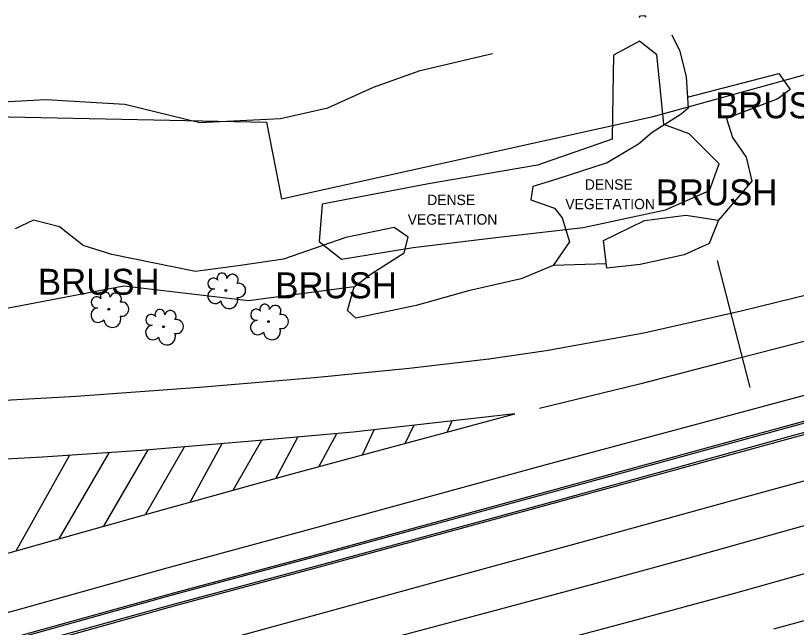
# Model space of a CAD drawing. Extents: x 2129547 to 2134906, y 657330 to 659734.
# Drawn here: x 2133105.5 to 2133315.8, y 658769 to 658933.8 of the extents above; entities that cross this region are included whole.
import ezdxf

# ---------------------------------------------------------------- set-up
doc = ezdxf.new("R2010")
doc.units = 0
for name, color, linetype in [('Default', 7, 'Continuous'), ('DR_X_Culvert', 7, 'Continuous'), ('PM_X_Edge_Line', 7, 'Continuous'), ('PM_X_Lane_Line', 7, 'Continuous'), ('PM_X_Transverse_Line', 7, 'Continuous'), ('PV_X_Curb', 7, 'Continuous'), ('PV_X_EOP2', 7, 'Continuous'), ('PV_X_Shoulder', 7, 'Continuous'), ('RD_X_Fence', 7, 'Continuous'), ('RD_X_Misc_Items', 7, 'Continuous'), ('SN_X_Cantilever_Overhead', 7, 'Continuous'), ('VG_X_Cells', 7, 'Continuous'), ('VG_X_Shrub_Line_Lt', 7, 'Continuous'), ('VG_X_Text', 7, 'Continuous'), ('VG_X_Tree_Line_Lt', 7, 'Continuous')]:
    doc.layers.add(name, color=color, linetype=linetype)

# ---------------------------------------------------------------- blocks, each defined once
blk = doc.blocks.new('CULVERT')
at = {"layer": 'Default'}
blk.add_lwpolyline([(-0.0508, 0.1143), (0, 0.0635), (0, -0.0635), (-0.0508, -0.1143)], dxfattribs=at)
blk = doc.blocks.new('TREE')
at = {"layer": 'VG_X_Cells'}
blk.add_circle((0, 0), 0.00305, dxfattribs=at)
for centre, radius, start, end in [((-0.0125, 0.0428), 0.0167, 354.0047, 205.9741), ((0.0232, 0.0359), 0.0197, 323.83, 165.0376), ((-0.042, 0.0237), 0.0187, 39.0625, 279.5412), ((-0.0362, -0.0197), 0.0251, 96.1722, 320.5737), ((0.0439, 0.0005), 0.0243, 259.1453, 101.4596), ((0.012, -0.0331), 0.029, 184.9476, 19.4572)]:
    blk.add_arc(centre, radius, start, end, dxfattribs=at)

msp = doc.modelspace()

# ---------------------------------------------------------------- linework, layer by layer
at = {"layer": 'PM_X_Edge_Line'}
for points in [[(2133329.04, 658861.1), (2133300.92, 658854.17), (2133274.71, 658848.24), (2133248.43, 658843.47), (2133232.93, 658841.23), (2133211.46, 658838.73), (2133186.01, 658836.22), (2133155.02, 658833.66), (2133121.79, 658831.17), (2133086.55, 658829.19), (2133054.09, 658828.41), (2133019.86, 658828.5), (2132985.53, 658829.46), (2132952.85, 658830.98), (2132915.52, 658833.61), (2132887.18, 658836.26), (2132858.31, 658839.93), (2132829.74, 658844.45), (2132808.54, 658848.31), (2132773.75, 658855.57)], [(2133352.86, 658840.89), (2133312.19, 658829.94), (2133247.7, 658812.58), (2133183.7, 658795.08), (2133146.25, 658784.96), (2133107.51, 658774.1), (2133073.85, 658764.93), (2133041.79, 658756.19), (2133011.05, 658747.8), (2132979.94, 658739.33), (2132948.72, 658730.94), (2132917.57, 658722.29), (2132887.16, 658713.87), (2132857, 658705.5), (2132818.68, 658695.21), (2132780.46, 658684.71), (2132740.98, 658673.64), (2132705.56, 658663.7), (2132666.4, 658652.81), (2132631.49, 658643.36), (2132595.52, 658633.47), (2132567.08, 658625.72), (2132529.28, 658615.18)], [(2133006.99, 658762.7), (2133037.72, 658771.1), (2133069.79, 658779.83), (2133103.39, 658788.99), (2133142.1, 658799.84), (2133179.64, 658810.26), (2133239.99, 658826.51), (2133196.39, 658821.58), (2133169.12, 658819.19), (2133139.39, 658816.63), (2133112.72, 658814.83), (2133086.2, 658813.46), (2133064.26, 658812.76), (2133033.29, 658812.66), (2133005.07, 658813.03), (2132970.88, 658814.09), (2132935.7, 658815.58), (2132903.64, 658817.26), (2132872, 658819.38), (2132835.28, 658822.67), (2132809.95, 658825.67), (2132783.95, 658829.71)], [(2132528.76, 658591.3), (2132572.65, 658603.2), (2132602.55, 658611.29), (2132644.66, 658622.9), (2132678.49, 658632.23), (2132709.33, 658640.79), (2132742.09, 658649.84), (2132779.08, 658660.22), (2132814.09, 658669.97), (2132851.16, 658680.16), (2132885.72, 658689.68), (2132917.4, 658698.33), (2132953.49, 658708.38), (2132988.45, 658717.87), (2133023.88, 658727.48), (2133061.03, 658737.93), (2133108.53, 658751.04), (2133150.67, 658762.63), (2133188.97, 658773.11), (2133222.93, 658782.47), (2133258.8, 658792.21), (2133300.07, 658803.6), (2133337.89, 658813.96)], [(2133309.7, 658768.6), (2133347.5, 658778.96)]]:
    msp.add_lwpolyline(points, dxfattribs=at)
at = {"layer": 'PM_X_Lane_Line'}
for points in [[(2133325.82, 658848.04), (2133297.69, 658840.83), (2133273.51, 658834.53), (2133246.62, 658827.98)], [(2133202.56, 658765), (2133233.48, 658773.28), (2133261.59, 658780.83), (2133286.58, 658787.68), (2133313.7, 658795.31), (2133339, 658802.3)], [(2133325.2, 658785.49), (2133298.77, 658778.04), (2133270.18, 658770.37), (2133241.97, 658762.79)]]:
    msp.add_lwpolyline(points, dxfattribs=at)
at = {"layer": 'PM_X_Transverse_Line'}
for p, q in [((2133221.73, 658821.59), (2133223.1, 658824.6)), ((2133210.38, 658818.54), (2133212.72, 658823.43)), ((2133187.21, 658812.3), (2133192.05, 658821.2)), ((2133198.93, 658815.46), (2133202.08, 658822.23)), ((2133152.49, 658802.73), (2133161.12, 658818.5)), ((2133164.13, 658805.96), (2133171.83, 658819.43)), ((2133175.61, 658809.14), (2133181.49, 658820.28)), ((2133129.27, 658796.25), (2133141.19, 658816.79)), ((2133140.53, 658799.4), (2133150.99, 658817.63)), ((2133105.69, 658789.63), (2133120.02, 658815.33)), ((2133117.26, 658792.88), (2133130.74, 658816.05))]:
    msp.add_line(p, q, dxfattribs=at)
at = {"layer": 'PV_X_Curb'}
for points in [[(2133354.62, 658834.11), (2133313.99, 658822.98), (2133249.15, 658805.18), (2133186.51, 658788.1), (2133148.3, 658777.86), (2133109.44, 658767.05), (2133075.85, 658757.65), (2133043.52, 658748.97), (2133012.69, 658740.69), (2132981.33, 658732.09), (2132950.79, 658723.65), (2132920.09, 658715.1), (2132889.35, 658706.83), (2132858.99, 658698.27), (2132820.58, 658687.77), (2132782.52, 658677.48), (2132742.93, 658666.63), (2132707.48, 658656.83), (2132668.28, 658645.96), (2132633.36, 658636.51), (2132602.69, 658628.08)], [(2133355.25, 658831.69), (2133314.65, 658820.57), (2133249.81, 658802.77), (2133187.16, 658785.68), (2133148.96, 658775.45), (2133110.11, 658764.65), (2133076.51, 658755.24), (2133044.17, 658746.56), (2133013.34, 658738.28), (2132981.99, 658729.68), (2132951.45, 658721.24), (2132920.75, 658712.69), (2132890.01, 658704.42), (2132859.66, 658695.87), (2132821.24, 658685.36), (2132783.18, 658675.06), (2132743.6, 658664.22), (2132708.14, 658654.42), (2132668.94, 658643.55), (2132634.02, 658634.09), (2132603.1, 658625.87)]]:
    msp.add_lwpolyline(points, dxfattribs=at)
at = {"layer": 'PV_X_EOP2'}
for points in [[(2133329.04, 658861.1), (2133300.92, 658854.17), (2133274.71, 658848.24), (2133248.43, 658843.47), (2133232.93, 658841.23), (2133232.68, 658841.2)], [(2133352.86, 658840.89), (2133312.19, 658829.94), (2133247.7, 658812.58), (2133183.7, 658795.08), (2133146.25, 658784.96), (2133107.51, 658774.1), (2133073.85, 658764.93), (2133041.79, 658756.19), (2133011.05, 658747.8), (2132979.94, 658739.33), (2132948.72, 658730.94), (2132917.57, 658722.29), (2132887.16, 658713.87), (2132857, 658705.5), (2132818.68, 658695.21), (2132780.46, 658684.71), (2132740.98, 658673.64), (2132705.56, 658663.7), (2132666.4, 658652.81), (2132631.49, 658643.36), (2132595.52, 658633.47), (2132567.08, 658625.72), (2132529.28, 658615.18)], [(2132529.63, 658631.32), (2132552.22, 658637.55), (2132563.39, 658640.65), (2132591.42, 658648.37), (2132627.43, 658658.26), (2132662.31, 658667.71), (2132701.4, 658678.58), (2132736.81, 658688.52), (2132776.33, 658699.59), (2132814.63, 658710.12), (2132852.93, 658720.4), (2132883.03, 658728.76), (2132913.44, 658737.18), (2132944.65, 658745.84), (2132975.91, 658754.24), (2133006.99, 658762.7), (2133037.72, 658771.1), (2133069.79, 658779.83), (2133103.39, 658788.99), (2133142.1, 658799.84), (2133179.64, 658810.26), (2133239.99, 658826.51)], [(2132528.76, 658591.3), (2132572.65, 658603.2), (2132602.55, 658611.29), (2132644.66, 658622.9), (2132678.49, 658632.23), (2132709.33, 658640.79), (2132742.09, 658649.84), (2132779.08, 658660.22), (2132814.09, 658669.97), (2132851.16, 658680.16), (2132885.72, 658689.68), (2132917.4, 658698.33), (2132953.49, 658708.38), (2132988.45, 658717.87), (2133023.88, 658727.48), (2133061.03, 658737.93), (2133108.53, 658751.04), (2133150.67, 658762.63), (2133188.97, 658773.11), (2133222.93, 658782.47), (2133258.8, 658792.21), (2133300.07, 658803.6), (2133337.89, 658813.96)], [(2133309.7, 658768.6), (2133347.5, 658778.96)]]:
    msp.add_lwpolyline(points, dxfattribs=at)
at = {"layer": 'PV_X_Shoulder'}
for points in [[(2132602.56, 658628.56), (2132633.23, 658636.99), (2132668.15, 658646.45), (2132707.34, 658657.31), (2132742.8, 658667.11), (2132782.39, 658677.96), (2132820.45, 658688.26), (2132858.86, 658698.76), (2132889.22, 658707.31), (2132919.96, 658715.58), (2132950.65, 658724.13), (2132981.19, 658732.57), (2133012.56, 658741.17), (2133043.39, 658749.45), (2133075.72, 658758.13), (2133109.31, 658767.54), (2133148.17, 658778.35), (2133186.38, 658788.58), (2133249.02, 658805.67), (2133313.86, 658823.46), (2133354.5, 658834.6)], [(2133355.38, 658831.21), (2133314.78, 658820.09), (2133249.94, 658802.29), (2133187.29, 658785.2), (2133149.09, 658774.97), (2133110.25, 658764.16), (2133076.65, 658754.76), (2133044.3, 658746.07), (2133013.47, 658737.79), (2132982.12, 658729.2), (2132951.59, 658720.76), (2132920.88, 658712.21), (2132890.15, 658703.93), (2132859.8, 658695.38), (2132821.37, 658684.88), (2132783.31, 658674.58), (2132743.73, 658663.74), (2132708.28, 658653.94), (2132669.07, 658643.07), (2132634.15, 658633.61), (2132603.23, 658625.39)]]:
    msp.add_lwpolyline(points, dxfattribs=at)
at = {"layer": 'RD_X_Fence'}
msp.add_lwpolyline([(2132862.2, 658871.41), (2132893.21, 658906.4), (2132919.58, 658910.31), (2132935.95, 658910.2), (2133025.5, 658908.09), (2133173.05, 658905.09), (2133177.13, 658884.47), (2133277.21, 658906.58), (2133331.89, 658921.65)], dxfattribs=at)
at = {"layer": 'RD_X_Misc_Items'}
msp.add_lwpolyline([(2133212.54, 658871.29), (2133234.86, 658874.04), (2133258.33, 658876.74), (2133280.52, 658881.5), (2133292.39, 658886.69), (2133294.99, 658893.89), (2133286.9, 658901.89), (2133280.1, 658904.48), (2133279.19, 658913.57), (2133278.22, 658923.23), (2133273.54, 658926.9), (2133266.51, 658923.13), (2133266.34, 658912.61), (2133266.15, 658900.51), (2133246.09, 658893.47), (2133216.71, 658888.43), (2133188.05, 658883.01), (2133187.25, 658872.96), (2133193.28, 658868.14)], close=True, dxfattribs=at)
at = {"layer": 'SN_X_Cantilever_Overhead'}
msp.add_line((2133303.28, 658833.6), (2133294.5, 658867.79), dxfattribs=at)
at = {"layer": 'VG_X_Shrub_Line_Lt'}
msp.add_line((2133264.61, 658866.9), (2133250.3, 658866.49), dxfattribs=at)
for points in [[(2133286.46, 658911.76), (2133311.03, 658918.2), (2133314.08, 658913.89), (2133310.78, 658911.33), (2133296.95, 658906.05), (2133298.52, 658900.91), (2133302.26, 658895.67), (2133303.73, 658889.22), (2133294.77, 658878.68)], [(2133196.68, 658860.72), (2133168.23, 658856.99), (2133134.64, 658860.95), (2133103.19, 658854.92), (2133090.89, 658849.45), (2133056.09, 658844.17), (2133036.34, 658845.04), (2133019.09, 658847.25), (2133012.2, 658854.08), (2133001.46, 658856.33)]]:
    msp.add_lwpolyline(points, dxfattribs=at)
at = {"layer": 'VG_X_Tree_Line_Lt'}
for points in [[(2133282.22, 658928.58), (2133284.35, 658924.15), (2133286.13, 658917.3), (2133286.64, 658908.83), (2133284.76, 658907.19), (2133276.9, 658902.31), (2133273.22, 658899.16), (2133264.8, 658894.16), (2133251.3, 658889.72), (2133244.83, 658887.78), (2133244.27, 658884.18), (2133250.66, 658881.87), (2133252.73, 658879.33), (2133254.67, 658872.89), (2133250.3, 658866.49), (2133241.65, 658862.84), (2133227.51, 658859.66), (2133213.4, 658855.73), (2133197.18, 658852.26), (2133194.87, 658854.33), (2133196.68, 658860.72), (2133201.29, 658864.23), (2133210.16, 658869.86), (2133211.23, 658874.12), (2133207.46, 658876.74), (2133194.41, 658873.97), (2133177.63, 658868.2), (2133166.08, 658866.46), (2133153.99, 658864.83), (2133131.39, 658869.4), (2133123.7, 658871.88), (2133117.38, 658876.93), (2133110.37, 658878.66), (2133105.38, 658876.33)], [(2133080.22, 658909.41), (2133113.68, 658911.18), (2133134.92, 658909.9), (2133155.09, 658904.95), (2133176.83, 658906.04), (2133189.62, 658908.97), (2133201.92, 658914.47), (2133214.48, 658919.01), (2133233.98, 658923.59)]]:
    msp.add_lwpolyline(points, dxfattribs=at)
msp.add_lwpolyline([(2133294.77, 658878.68), (2133292.29, 658872.38), (2133285.59, 658869.37), (2133273.7, 658866.78), (2133264.76, 658865.72), (2133263.82, 658873.24), (2133274.83, 658878.55), (2133285.96, 658879.99)], close=True, dxfattribs=at)

# ---------------------------------------------------------------- block references
at = {"layer": 'DR_X_Culvert', "xscale": 7.873999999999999, "yscale": 7.874, "rotation": 92.3278150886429}
msp.add_blockref('CULVERT', (2133274.33, 658933.73), dxfattribs=at)
at = {"layer": 'VG_X_Cells', "xscale": 78.74000000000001, "yscale": 78.74000000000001}
for p in [(2133162.1, 658859.74), (2133130.63, 658854.68), (2133173.6, 658851.36), (2133145.34, 658849.98)]:
    msp.add_blockref('TREE', p, dxfattribs=at)

# ---------------------------------------------------------------- texts
at = {"layer": 'VG_X_Text'}
for s, height, p in [('BRUSH', 7, (2133293.88, 658906.12)), ('DENSE', 2.8, (2133258.8, 658886.89)), ('BRUSH', 7, (2133277.89, 658882.66)), ('DENSE', 2.8, (2133216.36, 658882.75)), ('VEGETATION', 2.8, (2133253.55, 658881.62)), ('VEGETATION', 2.8, (2133211.11, 658877.48)), ('BRUSH', 7, (2133111.53, 658858.58)), ('BRUSH', 7, (2133175.43, 658857.64))]:
    msp.add_text(s, height=height, dxfattribs=at).set_placement(p)

doc.saveas('drawing.dxf')
